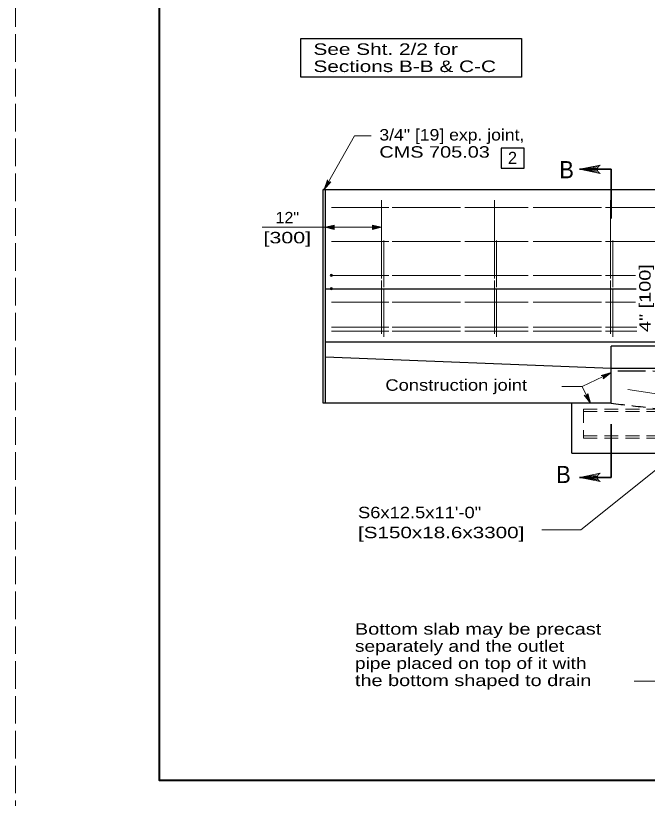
# Model space of a CAD drawing. Extents: x -1431.2 to -1397.2, y -1045.1 to -1001.1.
# Drawn here: x -1431.25 to -1422.47, y -1022.83 to -1011.95 of the extents above; entities that cross this region are included whole.
import ezdxf
from ezdxf.enums import TextEntityAlignment as Align

# ---------------------------------------------------------------- set-up
doc = ezdxf.new("R2010")
doc.units = 0
doc.header["$LTSCALE"] = 0.064
doc.header["$PDMODE"] = 32
doc.header["$PDSIZE"] = 0.032
doc.linetypes.add('LONG_DASHED', pattern=[7.5, 6, -1.5])
doc.linetypes.add('MEDIUM_DASHED', pattern=[4.5, 3, -1.5])
doc.layers.add('1', color=7, linetype='Continuous', lineweight=13)

msp = doc.modelspace()

# ---------------------------------------------------------------- hatches: boundary and pattern name
at = {"layer": '1'}
for points in [[(-1426.82033, -1014.92708), (-1426.94642, -1014.89558), (-1426.82033, -1014.86408)], [(-1426.28775, -1014.86408), (-1426.16167, -1014.89558), (-1426.28775, -1014.92708)]]:
    msp.add_hatch(color=256, dxfattribs=at).paths.add_polyline_path(points)

# ---------------------------------------------------------------- linework, layer by layer
for p, q in [((-1426.95808, -1014.37042), (-1426.53983, -1013.62342)), ((-1426.30917, -1013.62342), (-1426.53983, -1013.62342)), ((-1423.15275, -1014.05292), (-1423.4115, -1014.08908)), ((-1423.1615, -1014.07083), (-1423.4115, -1014.08908)), ((-1423.16417, -1014.08908), (-1423.4115, -1014.08908)), ((-1423.15958, -1014.11233), (-1423.4115, -1014.08908)), ((-1423.14967, -1014.12908), (-1423.4115, -1014.08908)), ((-1426.91258, -1014.25208), (-1426.95808, -1014.37042)), ((-1426.907, -1014.26), (-1426.95808, -1014.37042)), ((-1426.89983, -1014.2655), (-1426.95808, -1014.37042)), ((-1426.8795, -1014.26875), (-1426.95808, -1014.37042)), ((-1426.88892, -1014.269), (-1426.95808, -1014.37042)), ((-1426.16167, -1014.51992), (-1426.16167, -1015.60892)), ((-1424.59517, -1014.51992), (-1424.59517, -1015.60892)), ((-1422.98133, -1014.51992), (-1422.98133, -1015.60892)), ((-1426.8595, -1014.62258), (-1426.06217, -1014.62258)), ((-1426.0135, -1014.62258), (-1425.06425, -1014.62258)), ((-1425.00433, -1014.62258), (-1424.12633, -1014.62258)), ((-1424.05842, -1014.62258), (-1423.10917, -1014.62258)), ((-1423.05333, -1014.62258), (-1422.15367, -1014.62258)), ((-1427.82208, -1014.89558), (-1426.16167, -1014.89558)), ((-1426.8595, -1015.094), (-1426.06217, -1015.094)), ((-1426.13, -1015.07958), (-1426.13, -1015.72717)), ((-1426.0135, -1015.094), (-1425.06425, -1015.094)), ((-1425.00433, -1015.094), (-1424.12633, -1015.094)), ((-1424.5635, -1015.07958), (-1424.5635, -1015.72717)), ((-1424.05842, -1015.094), (-1423.10917, -1015.094)), ((-1423.05333, -1015.094), (-1422.15367, -1015.094)), ((-1422.94967, -1015.07958), (-1422.94967, -1015.72717)), ((-1426.8595, -1015.56392), (-1426.06217, -1015.56392)), ((-1426.0135, -1015.56392), (-1425.06425, -1015.56392)), ((-1425.00433, -1015.56392), (-1424.12633, -1015.56392)), ((-1424.05842, -1015.56392), (-1423.10917, -1015.56392)), ((-1423.05333, -1015.56392), (-1422.63275, -1015.56392)), ((-1426.16167, -1015.63667), (-1426.16167, -1016.37583)), ((-1424.59517, -1015.63667), (-1424.59517, -1016.37583)), ((-1422.98133, -1015.63667), (-1422.98133, -1016.37583)), ((-1426.13, -1015.76483), (-1426.13, -1016.41842)), ((-1424.5635, -1015.76483), (-1424.5635, -1016.41842)), ((-1422.94967, -1015.76483), (-1422.94967, -1016.41842)), ((-1426.8595, -1015.93567), (-1426.06217, -1015.93567)), ((-1426.0135, -1015.93567), (-1425.06425, -1015.93567)), ((-1425.00433, -1015.93567), (-1424.12633, -1015.93567)), ((-1424.05842, -1015.93567), (-1423.10917, -1015.93567)), ((-1423.05333, -1015.93567), (-1422.63275, -1015.93567)), ((-1426.8595, -1016.28475), (-1426.06217, -1016.28475)), ((-1426.8595, -1016.34033), (-1426.06217, -1016.34033)), ((-1426.0135, -1016.28475), (-1425.06425, -1016.28475)), ((-1426.0135, -1016.34033), (-1425.06425, -1016.34033)), ((-1425.00433, -1016.28475), (-1424.12633, -1016.28475)), ((-1425.00433, -1016.34033), (-1424.12633, -1016.34033)), ((-1424.05842, -1016.28475), (-1423.10917, -1016.28475)), ((-1424.05842, -1016.34033), (-1423.10917, -1016.34033)), ((-1423.05333, -1016.28475), (-1422.61842, -1016.28475)), ((-1423.05333, -1016.34033), (-1422.61842, -1016.34033)), ((-1422.91175, -1016.54658), (-1422.51542, -1016.54658)), ((-1422.9885, -1016.92092), (-1423.37483, -1017.10967)), ((-1423.09683, -1016.955), (-1422.97483, -1016.91467)), ((-1423.08892, -1016.96008), (-1422.97483, -1016.91467)), ((-1423.08183, -1016.96917), (-1422.97483, -1016.91467)), ((-1423.07892, -1016.97758), (-1422.97483, -1016.91467)), ((-1423.07875, -1016.98725), (-1422.97483, -1016.91467)), ((-1422.91175, -1016.85133), (-1422.51542, -1016.85133)), ((-1423.33358, -1017.23608), (-1423.26083, -1017.33992)), ((-1423.32383, -1017.23592), (-1423.26083, -1017.33992)), ((-1423.31533, -1017.23308), (-1423.26083, -1017.33992)), ((-1423.30633, -1017.22592), (-1423.26083, -1017.33992)), ((-1423.30133, -1017.21792), (-1423.26083, -1017.33992)), ((-1422.73958, -1017.15133), (-1421.74408, -1017.29542)), ((-1423.15275, -1018.33425), (-1423.4115, -1018.3705)), ((-1423.1615, -1018.35217), (-1423.4115, -1018.3705)), ((-1423.16417, -1018.3705), (-1423.4115, -1018.3705)), ((-1423.15958, -1018.39375), (-1423.4115, -1018.3705)), ((-1423.14967, -1018.4105), (-1423.4115, -1018.3705))]:
    msp.add_line(p, q, dxfattribs=at)
at = {"layer": '1', "lineweight": 25}
for p, q in [((-1426.97542, -1014.3715), (-1411.01725, -1014.3715)), ((-1426.97542, -1017.33992), (-1426.97542, -1014.3715)), ((-1426.94317, -1014.3715), (-1426.97225, -1014.3715)), ((-1426.94317, -1017.33992), (-1426.94317, -1014.3715)), ((-1426.94317, -1015.74883), (-1422.62633, -1015.74883)), ((-1426.94317, -1016.48792), (-1414.14858, -1016.48792)), ((-1422.97483, -1017.33992), (-1422.97483, -1016.54658)), ((-1423.51858, -1018.03408), (-1423.51858, -1017.33992)), ((-1423.51858, -1018.03408), (-1420.72517, -1018.03408))]:
    msp.add_line(p, q, dxfattribs=at)
at = {"layer": '1', "linetype": 'LONG_DASHED', "lineweight": 25}
msp.add_line((-1422.87942, -1016.89083), (-1421.56842, -1016.89417), dxfattribs=at)
at = {"layer": '1', "linetype": 'MEDIUM_DASHED'}
for p, q in [((-1423.35717, -1017.42058), (-1423.35717, -1017.824)), ((-1423.35717, -1017.45292), (-1414.62608, -1017.45292)), ((-1423.35717, -1017.79175), (-1414.62608, -1017.79175)), ((-1423.35717, -1017.824), (-1414.62608, -1017.824))]:
    msp.add_line(p, q, dxfattribs=at)
at = {"layer": '1', "linetype": 'LONG_DASHED'}
msp.add_lwpolyline([(-1431.24575, -1023.07983), (-1397.24575, -1023.07983), (-1397.24575, -1001.07983), (-1431.24575, -1001.07983)], close=True, dxfattribs=at)
at = {"layer": '1', "lineweight": 25}
for points in [[(-1397.74575, -1022.57983), (-1429.24575, -1022.57983), (-1429.24575, -1001.57983)], [(-1414.98508, -1017.33992), (-1414.98508, -1016.54658), (-1422.97483, -1016.54658)], [(-1426.94317, -1016.69625), (-1422.97483, -1016.85133), (-1420.22625, -1016.85133)], [(-1422.97483, -1017.33992), (-1426.94642, -1017.33992), (-1426.97542, -1017.33992)]]:
    msp.add_lwpolyline(points, dxfattribs=at)
at = {"layer": '1', "lineweight": 40}
msp.add_lwpolyline([(-1429.24575, -1001.57983), (-1397.74575, -1001.57983), (-1397.74575, -1022.57983), (-1429.24575, -1022.57983)], close=True, dxfattribs=at)
at = {"layer": '1', "lineweight": 25}
for points in [[(-1427.28567, -1012.2715), (-1424.21817, -1012.2715), (-1424.21817, -1012.80933), (-1427.28567, -1012.80933)], [(-1424.50033, -1013.79408), (-1424.50033, -1014.07208), (-1424.18308, -1014.07208), (-1424.18308, -1013.79408)]]:
    msp.add_lwpolyline(points, close=True, dxfattribs=at)
at = {"layer": '1'}
for points in [[(-1423.12567, -1014.14625), (-1423.4115, -1014.08908), (-1423.12567, -1014.03192)], [(-1426.86658, -1014.26258), (-1426.95808, -1014.37042), (-1426.91508, -1014.23567)], [(-1423.11108, -1016.95292), (-1422.97483, -1016.91467), (-1423.08583, -1017.00225)], [(-1423.27175, -1017.31642), (-1423.37483, -1017.10967), (-1423.65967, -1017.10967)], [(-1423.29917, -1017.20383), (-1423.26083, -1017.33992), (-1423.34858, -1017.22908)], [(-1421.80333, -1017.824), (-1423.39525, -1019.09867), (-1423.93392, -1019.09867)], [(-1423.12567, -1018.42767), (-1423.4115, -1018.3705), (-1423.12567, -1018.31333)], [(-1420.4325, -1020.36192), (-1422.13833, -1021.204), (-1422.65133, -1021.204)]]:
    msp.add_lwpolyline(points, dxfattribs=at)
at = {"layer": '1', "lineweight": 35}
for points in [[(-1422.97483, -1014.77492), (-1422.97483, -1014.08908), (-1423.4115, -1014.08908)], [(-1422.97483, -1017.63067), (-1422.97483, -1018.3705), (-1423.4115, -1018.3705)]]:
    msp.add_lwpolyline(points, dxfattribs=at)
at = {"layer": '1'}
for points in [[(-1426.82033, -1014.92708), (-1426.94642, -1014.89558), (-1426.82033, -1014.86408)], [(-1426.28775, -1014.86408), (-1426.16167, -1014.89558), (-1426.28775, -1014.92708)]]:
    msp.add_lwpolyline(points, close=True, dxfattribs=at)
at = {"layer": '1', "linetype": 'MEDIUM_DASHED'}
msp.add_lwpolyline([(-1423.35717, -1017.42058), (-1421.19792, -1017.42058), (-1414.62608, -1017.42058)], dxfattribs=at)
at = {"layer": '1'}
for centre in [(-1423.1026, -1014.08904), (-1423.1026, -1018.37041)]:
    msp.add_arc(centre, 0.06168, 112.08782, 247.91395, dxfattribs=at)
for centre, major_axis, start_param, end_param in [((-1426.88537, -1014.2393), (-0.02735, 0.01216), 0.2975606, 2.66817374), ((-1423.10848, -1016.98267), (0.02991, 0.00121), 5.52824227, 7.89885541), ((-1423.329, -1017.20639), (-0.02991, -0.0011), 0.82064998, 3.19126312)]:
    msp.add_ellipse(centre, major_axis=major_axis, ratio=0.999895, start_param=start_param, end_param=end_param, dxfattribs=at)
at = {"layer": '1', "linetype": 'MEDIUM_DASHED', "lineweight": 25}
msp.add_spline([(-1422.97483, -1017.33992), (-1422.42783, -1017.40283), (-1421.06567, -1017.52425), (-1420.3255, -1017.591), (-1420.24683, -1017.6235), (-1420.21467, -1017.66133), (-1420.19617, -1017.70508), (-1420.18708, -1017.73742)], degree=3, dxfattribs=at)
at = {"layer": '1'}
for p in [(-1426.8595, -1015.56392), (-1426.8595, -1015.74883)]:
    msp.add_point(p, dxfattribs=at)

# ---------------------------------------------------------------- texts
for s, height, width, p in [('See Sht. 2/2 for', 0.16, 1.35, (-1427.10867, -1012.50033)), ('Sections B-B & C-C', 0.16, 1.35, (-1427.10867, -1012.73833)), ('3/4" [19] exp. joint,', 0.1588, 1.15, (-1426.19283, -1013.68958)), ('CMS 705.03', 0.1588, 1.3, (-1426.19283, -1013.92775)), ('B', 0.2382, 0.95, (-1423.69242, -1014.21383)), ('Construction joint', 0.1588, 1.2, (-1426.1095, -1017.16658)), ('B', 0.2382, 0.95, (-1423.73592, -1018.44892)), ('S6x12.5x11\'-0"', 0.1588, 1.2, (-1426.49008, -1018.9375)), ('[S150x18.6x3300]', 0.1588, 1.35, (-1426.49008, -1019.21533)), ('Bottom slab may be precast', 0.1588, 1.3, (-1426.53225, -1020.55567)), ('separately and the outlet', 0.1588, 1.25, (-1426.53225, -1020.79383)), ('pipe placed on top of it with', 0.1588, 1.25, (-1426.53225, -1021.032)), ('the bottom shaped to drain', 0.1588, 1.3, (-1426.53225, -1021.27017))]:
    msp.add_text(s, height=height, dxfattribs=dict(at, width=width)).set_placement(p)
msp.add_text('2', height=0.1682, dxfattribs=at).set_placement((-1424.40617, -1014.01508))
for s, width, p in [('12"', 1.05, (-1427.47225, -1014.84042)), ('[300]', 1.4, (-1427.47229, -1015.11833))]:
    msp.add_text(s, height=0.1588, dxfattribs=dict(at, width=width)).set_placement(p, align=Align.CENTER)
at = {"layer": '1', "width": 1.3}
msp.add_text('4" [100]', height=0.1588, rotation=90, dxfattribs=at).set_placement((-1422.42467, -1016.34992))

doc.saveas('drawing.dxf')
